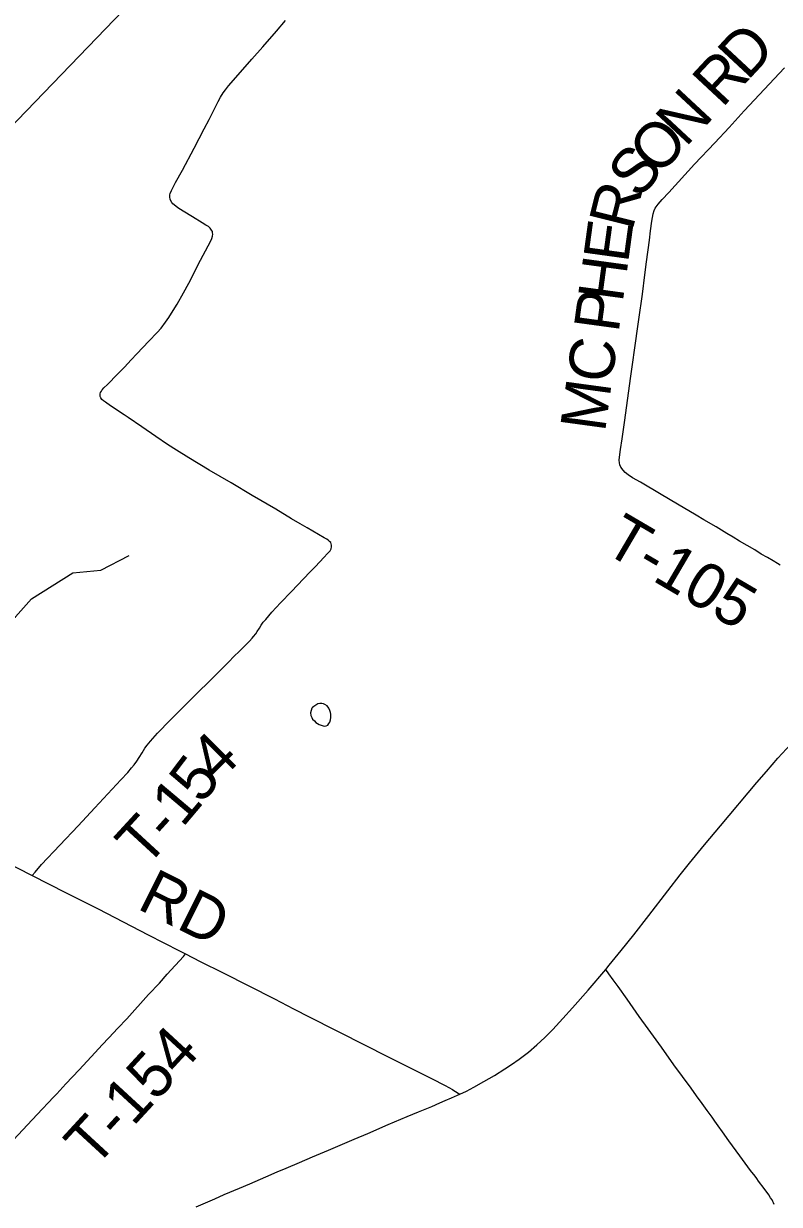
# Model space of a CAD drawing. Extents: x -19.5 to 44.1, y 0 to 22.
# Drawn here: x -16.527 to -15.579, y 18.108 to 19.589 of the extents above; entities that cross this region are included whole.
import ezdxf

# ---------------------------------------------------------------- set-up
doc = ezdxf.new("R2010")
doc.units = 0
for name, color, linetype in [('GM_X_County_Road', 7, 'Continuous'), ('GM_X_Minor_Lake', 7, 'Continuous'), ('GM_X_Minor_River', 7, 'Continuous'), ('GM_X_Township', 7, 'Continuous'), ('GM_X_Township_Road', 7, 'Continuous'), ('GM_X_Township_Road_Text', 7, 'Continuous')]:
    doc.layers.add(name, color=color, linetype=linetype)

msp = doc.modelspace()

# ---------------------------------------------------------------- linework, layer by layer
at = {"layer": 'GM_X_County_Road'}
for points in [[(-15.7973, 18.403), (-15.7928, 18.4083), (-15.7779, 18.4266), (-15.7621, 18.4466), (-15.7433, 18.4706), (-15.7194, 18.5016), (-15.7037, 18.5216), (-15.692, 18.5362), (-15.6732, 18.5593), (-15.6533, 18.5832), (-15.6076, 18.6373), (-15.5955, 18.6515), (-15.5813, 18.6679), (-15.5704, 18.6799), (-15.5615, 18.6887), (-15.5522, 18.697), (-15.5364, 18.71), (-15.5083, 18.7326), (-15.4767, 18.7587), (-15.4629, 18.7701)], [(-15.9802, 18.2466), (-15.972, 18.2503), (-15.9627, 18.2554), (-15.95, 18.2627), (-15.9368, 18.27), (-15.9238, 18.2784), (-15.9155, 18.2838), (-15.9059, 18.2905), (-15.8941, 18.2995), (-15.8837, 18.3083), (-15.8737, 18.3175), (-15.8637, 18.3277), (-15.8511, 18.3414), (-15.8389, 18.3547), (-15.8193, 18.3771), (-15.7973, 18.403)], [(-16.311, 18.1054), (-16.2876, 18.1155), (-16.2756, 18.1207), (-16.2567, 18.1287), (-16.2436, 18.1343), (-16.2236, 18.1429), (-16.2094, 18.1491), (-16.1979, 18.1539), (-16.1814, 18.1609), (-16.1648, 18.168), (-16.1448, 18.1765), (-16.1333, 18.1814), (-16.1127, 18.19), (-16.0957, 18.1975), (-16.07, 18.2085), (-16.0462, 18.2187), (-16.0321, 18.2244), (-16.0155, 18.2313), (-16.0052, 18.2356), (-15.9986, 18.2385), (-15.9905, 18.242), (-15.9832, 18.2453), (-15.9802, 18.2466)]]:
    msp.add_lwpolyline(points, dxfattribs=at)
at = {"layer": 'GM_X_Minor_Lake'}
msp.add_lwpolyline([(-16.166, 18.7308), (-16.1676, 18.7248), (-16.1669, 18.7214), (-16.1659, 18.719), (-16.1648, 18.7171), (-16.1625, 18.7148), (-16.1607, 18.7128), (-16.1588, 18.7113), (-16.1566, 18.7101), (-16.1528, 18.7089), (-16.1502, 18.708), (-16.1479, 18.7084), (-16.1456, 18.7094), (-16.1444, 18.7113), (-16.1432, 18.7132), (-16.1424, 18.7162), (-16.1419, 18.7192), (-16.1419, 18.7211), (-16.1422, 18.7234), (-16.1426, 18.7253), (-16.1433, 18.728), (-16.1447, 18.7307), (-16.1465, 18.7338), (-16.1495, 18.7354), (-16.1514, 18.7362), (-16.1533, 18.7366), (-16.156, 18.7367), (-16.1583, 18.736), (-16.161, 18.7345), (-16.1633, 18.7327), (-16.1652, 18.7316), (-16.166, 18.7308)], dxfattribs=at)
at = {"layer": 'GM_X_Minor_River'}
msp.add_lwpolyline([(-16.7713, 18.9302), (-16.7609, 18.9365), (-16.7488, 18.9344), (-16.7051, 18.9015), (-16.6733, 18.8587), (-16.652, 18.8411), (-16.6317, 18.83), (-16.6087, 18.8208), (-16.586, 18.8188), (-16.5647, 18.8251), (-16.5377, 18.8451), (-16.5176, 18.8678), (-16.4654, 18.9005), (-16.4304, 18.9039), (-16.3951, 18.9221)], dxfattribs=at)
at = {"layer": 'GM_X_Township'}
msp.add_lwpolyline([(-14.6789, 20.7469), (-15.2593, 20.802), (-15.6886, 20.3541), (-16.051, 19.976), (-16.1044, 19.9156), (-17.0212, 18.964), (-17.1488, 18.8309), (-17.1646, 18.7784), (-17.2501, 18.4952), (-17.3561, 18.1443), (-17.4643, 17.7858)], dxfattribs=at)
at = {"layer": 'GM_X_Township_Road'}
for points in [[(-16.5166, 18.5209), (-16.5129, 18.5252), (-16.5047, 18.5345), (-16.459, 18.583), (-16.4379, 18.6058), (-16.4053, 18.6407), (-16.3966, 18.6501), (-16.3921, 18.6558), (-16.3888, 18.6598), (-16.3855, 18.6642), (-16.3824, 18.669), (-16.3786, 18.6748), (-16.3769, 18.6778), (-16.3752, 18.6807), (-16.3724, 18.6842), (-16.3681, 18.6895), (-16.3593, 18.6993), (-16.3434, 18.7158), (-16.3271, 18.7321), (-16.312, 18.7469), (-16.2914, 18.7676), (-16.2752, 18.7835), (-16.2711, 18.7877), (-16.2623, 18.7967), (-16.258, 18.8008), (-16.2524, 18.8062), (-16.2472, 18.8115), (-16.244, 18.8149), (-16.2408, 18.8184), (-16.2389, 18.8206), (-16.2362, 18.824), (-16.2344, 18.827), (-16.2316, 18.8312), (-16.2294, 18.835), (-16.2269, 18.8385), (-16.2237, 18.842), (-16.2158, 18.8512), (-16.205, 18.8627), (-16.1914, 18.877), (-16.1762, 18.8931), (-16.1678, 18.9019), (-16.1618, 18.9079), (-16.1502, 18.9199), (-16.1464, 18.9241), (-16.1428, 18.9281), (-16.1414, 18.9304), (-16.141, 18.9331), (-16.141, 18.9351), (-16.1414, 18.9367), (-16.1422, 18.9383), (-16.1435, 18.9398), (-16.1449, 18.9412), (-16.1471, 18.9427), (-16.1502, 18.9445), (-16.1715, 18.9568), (-16.1803, 18.9618), (-16.1914, 18.9683), (-16.211, 18.9801), (-16.2405, 18.9974), (-16.2672, 19.0132), (-16.2944, 19.0294), (-16.32, 19.0447), (-16.3355, 19.0541), (-16.3469, 19.0616), (-16.3613, 19.0714), (-16.3792, 19.0837), (-16.3962, 19.0952), (-16.4012, 19.0988), (-16.4182, 19.1101), (-16.4246, 19.1143), (-16.4272, 19.1162), (-16.4291, 19.118), (-16.4305, 19.1198), (-16.4313, 19.1216), (-16.4315, 19.123), (-16.4314, 19.1248), (-16.4307, 19.1266), (-16.4298, 19.1282), (-16.4287, 19.1299), (-16.4266, 19.1323), (-16.4222, 19.1368), (-16.4095, 19.1495), (-16.4025, 19.1566), (-16.4013, 19.158), (-16.4008, 19.1584), (-16.3923, 19.1674), (-16.3852, 19.1753), (-16.3701, 19.1909), (-16.3598, 19.2017), (-16.355, 19.2073), (-16.3495, 19.2147), (-16.3454, 19.2205), (-16.3419, 19.226), (-16.3347, 19.2376), (-16.3266, 19.2515), (-16.3202, 19.2636), (-16.3055, 19.2924), (-16.2959, 19.3105), (-16.2931, 19.3159), (-16.2914, 19.3199), (-16.2905, 19.3227), (-16.2902, 19.325), (-16.2903, 19.3267), (-16.2906, 19.3284), (-16.2917, 19.3303), (-16.2932, 19.3327), (-16.2956, 19.3347), (-16.2987, 19.3366), (-16.3035, 19.3394), (-16.3156, 19.347), (-16.3273, 19.3539), (-16.3341, 19.3583), (-16.3366, 19.3602), (-16.34, 19.3631), (-16.3416, 19.3651), (-16.3433, 19.3679), (-16.3437, 19.3691), (-16.3441, 19.3717), (-16.3439, 19.3744), (-16.3435, 19.3763), (-16.342, 19.3799), (-16.3367, 19.3898), (-16.3279, 19.4055), (-16.3133, 19.4329), (-16.3007, 19.4571), (-16.2944, 19.4692), (-16.2886, 19.4809), (-16.2834, 19.4915), (-16.2804, 19.4969), (-16.2771, 19.5023), (-16.2742, 19.5063), (-16.2702, 19.5112), (-16.2524, 19.5318), (-16.2409, 19.5448), (-16.2272, 19.5601), (-16.2101, 19.5798), (-16.1988, 19.593)], [(-15.5784, 18.91), (-15.5819, 18.9121), (-15.5874, 18.9155), (-15.5945, 18.9196), (-15.6021, 18.924), (-15.6103, 18.9291), (-15.6294, 18.9403), (-15.6374, 18.9453), (-15.6453, 18.9498), (-15.6589, 18.958), (-15.6742, 18.9671), (-15.6838, 18.9729), (-15.7072, 18.9867), (-15.7277, 18.9986), (-15.7535, 19.0141), (-15.7635, 19.0198), (-15.769, 19.0233), (-15.7728, 19.0263), (-15.7755, 19.0293), (-15.7782, 19.0331), (-15.7795, 19.0358), (-15.7801, 19.0386), (-15.7804, 19.0418), (-15.7801, 19.0457), (-15.7787, 19.0551), (-15.7765, 19.0686), (-15.7732, 19.092), (-15.7661, 19.1442), (-15.7628, 19.1677), (-15.7617, 19.1769), (-15.7557, 19.2181), (-15.7513, 19.2501), (-15.7483, 19.2741), (-15.746, 19.2907), (-15.7424, 19.3178), (-15.7411, 19.3295), (-15.7393, 19.3417), (-15.7376, 19.3508), (-15.7365, 19.3549), (-15.7354, 19.3576), (-15.7341, 19.3596), (-15.7314, 19.363), (-15.7266, 19.3685), (-15.7181, 19.3776), (-15.6859, 19.4129), (-15.6602, 19.4399), (-15.6424, 19.459), (-15.6236, 19.4797), (-15.5732, 19.5337)], [(-16.8871, 18.7099), (-16.8608, 18.6964), (-16.8382, 18.6848), (-16.8068, 18.6691), (-16.7981, 18.6646), (-16.7894, 18.6603), (-16.7597, 18.645), (-16.7427, 18.6363), (-16.7105, 18.6201), (-16.679, 18.6041), (-16.6601, 18.5946), (-16.6353, 18.5817), (-16.6115, 18.5696), (-16.5589, 18.5427), (-16.5433, 18.5345), (-16.5353, 18.5305), (-16.5166, 18.5209)], [(-16.5166, 18.5209), (-16.475, 18.4997), (-16.434, 18.4789), (-16.371, 18.4466), (-16.3317, 18.4264), (-16.3241, 18.4225)], [(-16.5402, 18.1893), (-16.5223, 18.2082), (-16.5104, 18.221), (-16.4897, 18.2427), (-16.4856, 18.2472), (-16.478, 18.2555), (-16.4742, 18.2595), (-16.4578, 18.2771), (-16.4376, 18.2988), (-16.4286, 18.3085), (-16.4204, 18.3172), (-16.4092, 18.3296), (-16.398, 18.3411), (-16.3706, 18.3715), (-16.357, 18.386), (-16.3471, 18.3971), (-16.327, 18.4192), (-16.3241, 18.4225)], [(-16.3241, 18.4225), (-16.3058, 18.4132), (-16.2769, 18.3986), (-16.2126, 18.366), (-16.1887, 18.3536), (-16.1814, 18.3499), (-16.1757, 18.3469), (-16.1285, 18.3231), (-16.1031, 18.3101), (-16.0676, 18.2923), (-16.0459, 18.2814), (-16.0333, 18.275), (-16.0157, 18.2663), (-15.9986, 18.2575), (-15.9894, 18.2523), (-15.9878, 18.2513), (-15.9802, 18.2466)], [(-15.5861, 18.1083), (-15.5867, 18.1104), (-15.5875, 18.1122), (-15.5886, 18.1141), (-15.5904, 18.1168), (-15.5928, 18.1202), (-15.5985, 18.1283), (-15.6056, 18.1377), (-15.6079, 18.1408), (-15.61, 18.1437), (-15.6157, 18.151), (-15.6291, 18.1694), (-15.643, 18.1882), (-15.6509, 18.1992), (-15.6563, 18.2069), (-15.6602, 18.2127), (-15.6638, 18.2176), (-15.6699, 18.2261), (-15.6764, 18.2349), (-15.6833, 18.2445), (-15.6901, 18.254), (-15.7117, 18.2835), (-15.7274, 18.3056), (-15.7442, 18.3286), (-15.7551, 18.3442), (-15.7704, 18.3658), (-15.7816, 18.3815), (-15.7877, 18.39), (-15.7932, 18.3975), (-15.7973, 18.403)]]:
    msp.add_lwpolyline(points, dxfattribs=at)

# ---------------------------------------------------------------- texts
at = {"layer": 'GM_X_Township_Road_Text'}
for s, height, rotation, p in [('D', 0.0568, 47.0637, (-15.6195, 19.5168)), ('R', 0.0568, 47.0649, (-15.6513, 19.4826)), ('N', 0.0568, 47.0624, (-15.6972, 19.4332)), ('O', 0.0568, 47.1165, (-15.7313, 19.3966)), ('S', 0.0568, 49.8422, (-15.7555, 19.3678)), ('R', 0.0568, 75.9297, (-15.7638, 19.3286)), ('E', 0.0568, 82.1584, (-15.7693, 19.2881)), ('H', 0.0568, 82.2429, (-15.776, 19.2386)), ('P', 0.0568, 82.2432, (-15.7812, 19.2006)), ('C', 0.0568, 82.2435, (-15.7898, 19.137)), ('M', 0.0568, 82.2437, (-15.7982, 19.0759)), ('T-105', 0.05682, 329.6065, (-15.8021, 18.9279)), ('4', 0.0568, 45.1601, (-16.2837, 18.6355)), ('5', 0.0568, 52.8331, (-16.3035, 18.6091)), ('1', 0.0568, 49.8816, (-16.3281, 18.5799)), ('T', 0.0568, 47.3856, (-16.3743, 18.5293)), ('-', 0.0568, 47.7272, (-16.3453, 18.5608)), ('RD', 0.05682, 333.4379, (-16.3864, 18.48)), ('T-154', 0.05682, 47.3694, (-16.4386, 18.1525))]:
    msp.add_text(s, height=height, rotation=rotation, dxfattribs=at).set_placement(p)

doc.saveas('drawing.dxf')
